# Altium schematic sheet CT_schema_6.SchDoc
size 287 x 160 mm
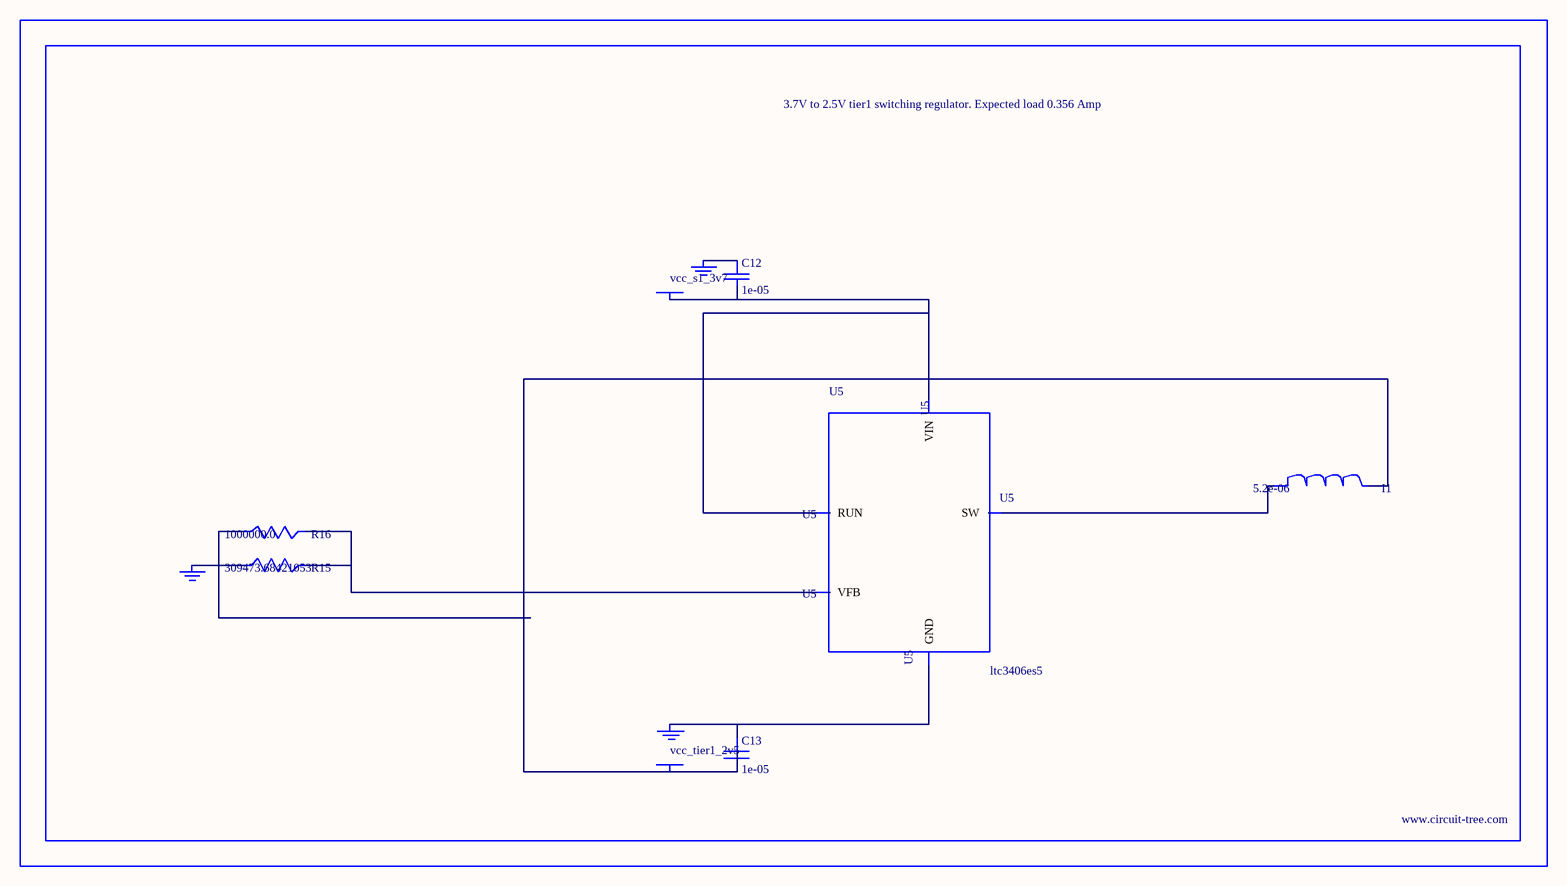
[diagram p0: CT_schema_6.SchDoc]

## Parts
BORDER5  (no value)
C12  1e-05  [C0805]
C13  1e-05  [C0805]
GND_INSTANCE_5_0  (no value)
GND_INSTANCE_5_1  (no value)
GND_INSTANCE_5_2  (no value)
I1  5.2e-06  [DR1040]
POWER_INSTANCE_5_0  vcc_tier1_2v5
POWER_INSTANCE_5_1  vcc_s1_3v7
R15  309473.68421053  [R0603]
R16  1000000.0  [R0603]
U5  ltc3406es5  [TSOT-23-5]

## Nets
NetC12_1: C12.1 GND_INSTANCE_5_1.0(GND)
NetC12_2: C12.2 POWER_INSTANCE_5_1.0(PWR) U5.1(RUN) U5.4(VIN)
NetC13_1: C13.1 GND_INSTANCE_5_0.0(GND) U5.2(GND)
NetC13_2: C13.2 I1.2 POWER_INSTANCE_5_0.0(PWR) R16.1
NetGND_INSTANCE_5_2_0: GND_INSTANCE_5_2.0(GND) R15.1
NetI1_1: I1.1 U5.3(SW)
NetR15_2: R15.2 R16.2 U5.5(VFB)

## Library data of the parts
BORDER5 = BORDER_PAGE5
C12 C13 = C0805C106K8RACTU
GND_INSTANCE_5_0-GND_INSTANCE_5_2 = GND
I1 = DR1040-5R2-R
POWER_INSTANCE_5_0 POWER_INSTANCE_5_1 = PWR
R15 = R15
R16 = RC0603JR-071ML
